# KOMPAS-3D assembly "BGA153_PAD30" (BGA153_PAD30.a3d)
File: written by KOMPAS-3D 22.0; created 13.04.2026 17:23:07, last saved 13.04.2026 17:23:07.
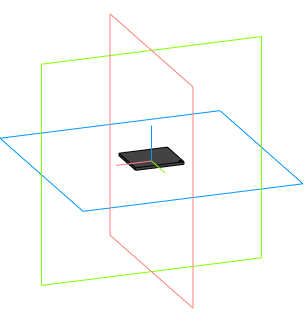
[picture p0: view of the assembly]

Document properties: Автор: Andrey; Полное имя файла: C:\Users\User1\Documents\BGA153_PAD30.a3d

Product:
- Component [detail]: THGBMNG5D1LBAIT  | qty 1  | source file: THGBMNG5D1LBAIT.m3d
- Part/product: BGA153_PAD30
    Комментарий: BGA153_PAD30

Referenced files in C:\Users\User1\Documents\: THGBMNG5D1LBAIT.m3d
